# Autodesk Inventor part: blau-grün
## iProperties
Created: 2004-10
Part Number: blau-grün
Document SubType Name: Modeling
Designer: sahrens
Manufacturer: Standard
Standards Organization: Custom
Author: sahrens
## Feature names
1. Extrusion1
2. Rundung2 [Fillet]
